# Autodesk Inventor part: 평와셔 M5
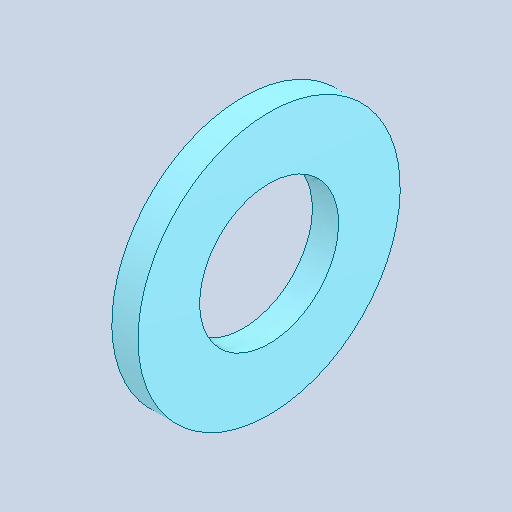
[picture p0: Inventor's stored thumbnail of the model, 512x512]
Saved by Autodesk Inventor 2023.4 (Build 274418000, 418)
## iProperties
Created: 2024-09
Part Number: 평와셔 M5
Material: 강철, 연강
Description: 평면 와셔
Document SubType Name: Modeling
Designer: 11
Density: 7.85 g/cm^3
Appearance: 기본값
Author: jhkim
Sending System: Autodesk Inventor 2025
Preprocessor: ST-DEVELOPER v20
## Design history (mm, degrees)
node "평와셔 M51"
node "솔리드1"
body "Solid1"
